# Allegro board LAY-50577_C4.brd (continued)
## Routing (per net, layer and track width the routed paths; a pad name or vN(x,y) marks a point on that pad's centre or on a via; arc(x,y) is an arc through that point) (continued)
N103962432: length 19.6
  TOP w0.119: J53.2 5.12,115.79 5.32,115.59 6.6,115.59 6.71,115.7 7.51,115.7 7.94,115.27 9.05,115.27 U51.3 9.66,115.21 v1(9.99,115.54)
  BOTTOM w0.119: v1(9.99,115.54) 10.01,115.52 10.27,115.52 11.54,116.79 12.36,116.79 12.48,116.91 12.48,117.14 12.59,117.26 12.83,117.26 12.95,117.14 12.95,116.91 13.07,116.79 21.83,116.79 R812.1
N103962456: length 19.4
  TOP w0.119: J53.3 5.14,115.14 5.34,115.34 6.7,115.34 6.84,115.21 U51.2 7.66,115.21 7.84,115.02 8.4,115.02 8.71,114.72 9.59,114.72 9.95,115.08 10.32,115.08 v1(10.42,114.98)
  BOTTOM w0.119: R813.1 21.7,116.55 11.64,116.55 10.43,115.34 10.43,115.31 10.42,115.3 v1(10.42,114.98)
N103962999: length 2.4
  TOP w0.127: R815.1 12.2,99.12 U52.A3
N103963079: length 4
  TOP w0.127: U52.A1 12.7,99.92 13.32,100.54 R817.1 ; R816.2 R817.1 ; R817.1 R818.2
N104012170: length 2.4
  TOP w0.127: R821.1 JP7.2
N104016532: length 1.7
  TOP w0.127: R831.1 44.18,108.15 U58.7
N104016534: length 1.8
  TOP w0.127: R832.1 43.8,107.65 U58.6
N104016623: length 2.7
  TOP w0.127: R902.2 R835.1 33.89,101.04 33.75,100.9 U57.4
N104016749: length 2.3
  TOP w0.127: R833.1 29.58,105.76 R903.2 30.21,105.74 30.32,105.63 U59.4
N104016751: length 2.5
  TOP w0.127: U56.4 34.52,97.35 R901.2 R834.1
N104017363: length 5.8
  TOP w0.203: U60.2 42.73,97.67 42.81,97.59 v1(42.81,97.49)
  BOTTOM w0.381: R842.1 41.56,98.26 ; R842.1 41.13,97.85 ; R842.1 40.7,98.26 ; JP5.2 42.07,93.04 ; JP5.2 40.19,93.04 ; JP5.2 41.13,93.98 ; JP5.2 41.13,92.1
N104034773: length 2.2
  TOP w0.127: R846.1 38.09,113.88 U61.14
N104034775: length 1.9
  TOP w0.127: R847.1 37.7,114.12 37.96,114.38 U61.13
N104034777: length 2.2
  TOP w0.127: R848.2 42.65,113.88 U61.3
N104034811: length 4
  TOP w0.127: U61.9 40.12,117.43 R849.2 39.09,117.43 38.58,117.95 Q15.3
N104034835: length 2
  TOP w0.127: R1078.2 43.03,115.78 42.64,115.38 U61.6
N104105294: length 1.2
  TOP w0.127: R854.2 34.89,107.64 D30.A
N104105296: length 1.2
  TOP w0.127: D29.A 32.35,107.64 R853.2
N104315925: length 3.8
  TOP w0.381: U42.3 68.86,106.2 C277.1 C276.1 R653.2
N104599012: length 1.9
  TOP w0.127: v1(113.14,124.28) 113.25,124.17 D31.C
  BOTTOM w0.127: v1(113.14,124.28) 112.81,123.95 Q19.3
N104599036: length 3.2
  BOTTOM w0.127: R875.1 116.31,125.68 R876.1 114.91,125.15 114.99,125.07 Q19.1
N104599080: length 2
  TOP w0.127: D32.C 113.25,120.49 v1(113.01,120.73)
  BOTTOM w0.127: Q20.3 112.81,120.53 v1(113.01,120.73)
N104599094: length 2.7
  BOTTOM w0.127: Q20.1 116.43,120.86 R879.1 117.7,120.85 R878.1
N104600982: length 2
  TOP w0.127: D33.C 113.25,116.93 v1(113.01,117.17)
  BOTTOM w0.127: v1(113.01,117.17) 112.81,116.97 Q21.3
N104600995: length 2.7
  BOTTOM w0.127: R885.1 117.7,117.29 R886.1 115.04,117.29 Q21.1
N104601399: length 1.9
  TOP w0.127: D35.C 113.25,113.25 113.01,113.49 v1(113.01,113.53)
  BOTTOM w0.127: v1(113.01,113.53) 112.81,113.32 Q23.3
N104601413: length 2.7
  BOTTOM w0.127: R891.1 117.7,113.74 R892.1 115.06,113.74 Q23.1
N104649727: length 1.7
  TOP w0.127: U48.7 160.69,27.19 R804.2
N104649749: length 2.9
  TOP w0.127: R800.2 R803.1 160,18.87 160.04,18.92 U48.1
N104653681: length 1.9
  TOP w0.381: 55.23,134.06 54.75,134.54 J60.1
N104654018: length 21.2
  TOP w0.381: 49.27,137.42 J60.7 48.47,138.55 ; C528.1 49.82,133.3 ; C528.1 49.38,133.7 ; C528.1 R1327.1 ; 56.38,135.42 J60.9 55.67,134.61 ; 58.42,138.55 J60.8 57.62,137.42 ; R1327.1 48.24,133.7 ; R1327.1 47.81,133.3 ; 51.22,134.61 J60.6 50.51,135.42
  L3_INT_1 w0.381: J60.6 51.22,136.24 ; J60.6 51.22,134.61 ; J60.6 51.93,135.42 ; J60.6 50.51,135.42 ; 55.67,134.61 J60.9 ; J60.9 55.67,136.24 ; J60.9 56.38,135.42 ; J60.9 54.96,135.42 ; J60.7 50.06,138.55 ; J60.7 49.27,137.42 ; J60.7 48.49,138.55 ; 56.84,138.55 J60.8 ; J60.8 57.62,137.42 ; J60.8 58.41,138.55
N104654056: length 2.4
  TOP w0.127: U74.3 53.02,133.98 52.8,134.21 J60.4
N105054073: length 10.8
  TOP w0.127: J67.9 188.7,26.24 187.68,27.26 R1021.1
  BOTTOM w0.127: J67.9 J67.7 J67.5 J67.3
N105054132: length 15.2
  TOP w0.127: R1022.2 188.06,24.97 192.89,24.97 193.78,25.86 193.78,32.46 192.39,33.85 J67.4
N105054134: length 5.7
  TOP w0.127: R1023.2 188.82,32.46 191.24,32.46 J67.6
N105054136: length 5.2
  TOP w0.127: J67.8 191.24,29.92 R1024.2
N105054138: length 5.8
  TOP w0.127: R1025.2 189.2,27.38 191.24,27.38 J67.10
N105070687: length 3.7
  TOP w0.127: U115.5 62.25,93.46 62.46,93.68 62.46,94.56 R1028.2
N105070691: length 2.2
  TOP w0.127: R1033.2 57.87,93.06 U115.7
N105070693: length 2.2
  TOP w0.127: R1034.1 57.87,92.26 U115.9
N105070700: length 3.2
  TOP w0.127: R1036.2 R1035.1 62.72,92.03 62.48,92.26 U115.2
N105070744: length 2
  TOP w0.127: U115.8 R1029.1
N105070750: length 2.4
  TOP w0.127: U115.6 58.36,93.46 R1030.1
N105070826: length 3.3
  TOP w0.127: U115.3 62.59,92.66 62.85,92.92 R1031.1 R1038.2
N105070844: length 3.2
  TOP w0.127: R1032.1 62.85,94.05 62.85,93.55 62.36,93.06 U115.4
N105164696: length 3.4
  TOP w0.127: R1043.1 R1044.1 187.46,87.67 v1(188.58,87.67)
  BOTTOM w0.127: U117.2 v1(188.58,87.67)
N105165362: length 3.1
  BOTTOM w0.127: U118.2 116.59,87.67 R1045.2 R1046.2
N105165453: length 2.5
  BOTTOM w0.127: R1047.1 R1048.1 153.39,123.77 153.57,123.95 U119.2
N105216901: length 111.3
  TOP w0.127: R1067.2 v1(148.82,84.79)
  L3_INT_1 w0.127: v1(145.4,38.05) 145.46,38.11 145.46,46.1 143.68,47.88 143.68,67.47 149.28,73.07 149.28,74.68 149.08,74.88 149.08,78.95 152.63,82.5 152.63,83.26 151.62,84.28 149.33,84.28 v1(148.82,84.79)
  BOTTOM w0.127: v1(145.4,38.05) 145.9,38.56 158.1,38.56 167.24,29.42 168.15,29.42 169.3,28.27 171.38,28.27 173.21,26.44 173.21,19 173.59,18.62 173.59,15.45 J69.3
N105216903: length 114.1
  TOP w0.127: R1064.2 v1(143.74,84.79)
  L3_INT_1 w0.127: v1(143.74,84.79) 144.63,83.9 151.36,83.9 152.13,83.14 152.13,82.5 148.57,78.95 148.57,74.75 148.88,74.45 148.88,73.99 148.37,73.48 147.94,73.48 147.3,72.85 147.3,71.78 143.3,67.78 143.3,47.72 145.07,45.94 145.07,38.75 v1(144.38,38.05)
  BOTTOM w0.127: J69.5 179.69,7.91 172.83,14.77 172.83,18.37 172.45,18.75 172.45,23.32 168.64,27.13 168.64,27.94 167.93,28.65 166.99,28.65 158.1,37.54 144.89,37.54 v1(144.38,38.05)
N105216905: length 101
  TOP w0.127: R1069.2 v1(140.95,65.99)
  BOTTOM w0.127: J69.7 177.15,8.71 172.07,13.79 172.07,18.11 170.92,19.26 170.92,23.73 158.83,35.82 148.62,35.82 147.68,34.88 143.24,34.88 141.9,36.22 134.66,36.22 130.23,40.65 130.23,44.73 130.66,45.16 132.57,45.16 137.78,50.37 138.66,50.37 140,51.7 140,54.83 141.97,56.8 141.97,63.76 140.95,64.77 v1(140.95,65.99)
N105216907: length 94.9
  TOP w0.127: v1(141.33,62.06) R1066.2
  BOTTOM w0.127: v1(141.33,62.06) 141.33,56.97 138.79,54.43 138.79,51.64 138.54,51.39 137.71,51.39 132.25,45.93 130.35,45.93 129.62,45.2 129.62,40.24 134.25,35.61 141.11,35.61 142.47,34.24 159.46,34.24 170.16,23.54 170.16,11.25 J69.9
N105216909: length 83
  TOP w0.127: R1068.2 v1(138.32,51.9)
  BOTTOM w0.127: v1(138.32,51.9) 137.78,51.9 132.19,46.31 130.19,46.31 129.31,45.43 129.31,40.04 134.05,35.3 140.78,35.3 142.14,33.94 159.32,33.94 168.38,24.88 168.38,12.27 172.07,8.59 J69.11
N105216911: length 87.9
  TOP w0.127: R1065.2 v1(139.05,56.47)
  BOTTOM w0.127: v1(139.05,56.47) 138.66,56.47 137.81,55.62 137.81,53.13 131.75,47.07 129.87,47.07 128.63,45.83 128.63,40.85 127.87,40.08 127.87,39.58 128.12,39.32 128.94,39.32 133.57,34.69 140.37,34.69 141.74,33.33 158.63,33.33 166.1,25.86 166.1,11.51 169.53,8.08 J69.13
N105216913: length 91.8
  TOP w0.127: R1073.2 138.02,60.28 v1(137.65,60.28)
  BOTTOM w0.127: J69.15 166.99,8.46 165.46,9.98 165.46,25.48 158.22,32.72 141.2,32.72 139.84,34.08 133.11,34.08 128.63,38.56 127.49,38.56 126.4,39.65 126.4,40.39 127.89,41.88 127.89,46.16 129.56,47.83 131.38,47.83 137.01,53.47 137.01,56.26 137.98,57.23 137.98,59.95 v1(137.65,60.28)
N105216915: length 105.9
  TOP w0.127: R1071.2 126.01,67.08 127.13,67.08 127.4,66.82 129.46,66.82 129.86,66.41 134.15,66.41 v1(134.85,65.71)
  BOTTOM w0.127: J69.17 163.43,7.83 163.43,25.48 156.8,32.11 151.9,32.11 151.11,31.32 141.46,31.32 140.06,32.72 132.44,32.72 131.93,33.23 131.93,34.11 128.25,37.8 127.23,37.8 125.71,39.32 125.71,40.97 126.98,42.24 126.98,46.33 129.24,48.59 130.92,48.59 136.23,53.9 136.23,60.78 134.85,62.16 v1(134.85,65.71)
N105216917: length 93.9
  TOP w0.127: R1072.2 132.7,62.69 v1(132.57,62.82)
  BOTTOM w0.127: v1(132.57,62.82) 135.36,60.02 135.36,58.5 134.73,57.86 134.73,53.29 130.79,49.35 128.93,49.35 125.96,46.39 125.96,43.39 124.95,42.37 124.95,39.07 126.98,37.04 127.74,37.04 131.04,33.73 131.04,32.97 131.96,32.06 139.58,32.06 141.08,30.56 153.02,30.56 153.27,30.81 157.21,30.81 162.67,25.35 162.67,7.57 J69.19
N105217449: length 111.1
  TOP w0.127: R1056.1 v1(152.63,84.79)
  L3_INT_1 w0.127: v1(146.41,38.05) 147.61,39.25 147.61,44.67 144,48.28 144,67.36 149.61,72.97 149.61,74.73 150.27,75.39 150.27,79.63 153.78,83.14 153.78,83.64 v1(152.63,84.79)
  BOTTOM w0.127: J69.4 180.83,5.67 180.83,7.49 173.21,15.11 173.21,18.49 172.83,18.88 172.83,26.29 171.22,27.89 169.17,27.89 168.01,29.05 167.1,29.05 158.1,38.05 v1(146.41,38.05)
N105217451: length 111.3
  TOP w0.127: R1054.1 v1(157.97,84.79)
  L3_INT_1 w0.127: v1(146.41,37.04) 147.96,38.59 147.96,44.88 145.01,47.83 145.01,54.94 145.4,55.32 145.4,62.09 144.76,62.72 144.76,67.26 150.41,72.91 150.41,73.7 151.11,74.4 151.11,79.07 154.16,82.12 156.06,82.12 157.97,84.03 v1(157.97,84.79)
  BOTTOM w0.127: v1(146.41,37.04) 146.54,37.16 157.97,37.16 166.9,28.23 167.84,28.23 168.26,27.82 168.26,27 172.07,23.19 172.07,18.62 172.45,18.24 172.45,14.43 178.54,8.34 178.54,5.41 J69.6
N105217453: length 97.3
  TOP w0.127: v1(139.43,54.24) 134.97,54.24 133.58,55.63 R1059.1
  BOTTOM w0.127: J69.8 176,5.41 176,8.84 170.54,14.3 170.54,23.6 158.63,35.51 148.95,35.51 147.99,34.55 142.93,34.55 141.57,35.91 134.46,35.91 129.92,40.44 129.92,44.96 130.51,45.54 132.41,45.54 137.74,50.88 138.54,50.88 139.43,51.77 v1(139.43,54.24)
N105217455: length 91
  TOP w0.127: v1(147.3,47.2) 147.36,47.25 R1057.1
  BOTTOM w0.127: J69.10 175.88,3 185.27,3 187.05,4.78 187.05,36.02 174.73,48.34 163.43,48.34 162.54,47.45 147.55,47.45 v1(147.3,47.2)
N105217467: length 89.7
  TOP w0.127: v1(138.66,55.7) 138.41,55.96 R1058.1
  BOTTOM w0.127: J69.12 170.8,5.54 170.8,8.71 168,11.51 168,24.64 159.01,33.63 141.94,33.63 140.58,35 133.85,35 129.01,39.84 129.01,45.7 130.02,46.71 132.06,46.71 138.28,52.94 138.28,55.32 v1(138.66,55.7)
N105217469: length 78.8
  TOP w0.127: v1(190.99,49.74) 190.48,50.24 180.71,50.24 R1055.1
  BOTTOM w0.127: v1(190.99,49.74) 187.43,46.18 187.43,4.62 185.43,2.62 171.18,2.62 J69.14
N105217471: length 100.9
  TOP w0.127: R1063.1 v1(135.87,64.47)
  BOTTOM w0.127: v1(135.87,64.47) 137.27,64.47 138.54,63.2 138.54,62.44 138.28,62.18 138.28,56.87 137.43,56.02 137.43,53.33 131.55,47.45 129.72,47.45 128.25,45.98 128.25,40.97 127.49,40.21 127.49,39.45 128,38.94 128.76,38.94 133.31,34.39 140.04,34.39 141.41,33.02 158.49,33.02 165.77,25.74 165.77,10.7 168.32,8.14 168.32,5.6 J69.16
N105217473: length 96.4
  TOP w0.127: v1(137.27,62.82) R1061.1
  BOTTOM w0.127: J69.18 165.72,5.54 165.72,8.33 163.81,10.24 163.81,26.62 158.02,32.41 141,32.41 139.64,33.78 132.78,33.78 128.38,38.18 127.36,38.18 126.07,39.47 126.07,40.69 127.49,42.12 127.49,46.3 129.4,48.21 131.17,48.21 136.61,53.65 136.61,60.12 137.27,60.78 v1(137.27,62.82)
N105217475: length 100
  TOP w0.127: R1062.1 131.3,64.83 v1(131.44,64.97)
  BOTTOM w0.127: J69.20 163.18,5.54 163.18,7.44 163.05,7.57 163.05,25.41 156.66,31.8 152.1,31.8 151.24,30.94 141.33,30.94 139.91,32.36 132.16,32.36 131.55,32.97 131.55,33.86 128,37.42 127.11,37.42 125.33,39.19 125.33,41.23 126.47,42.37 126.47,46.36 129.08,48.97 130.84,48.97 135.24,53.37 135.24,56.47 135.79,57.03 135.79,60.23 131.44,64.58 v1(131.44,64.97)
N105256205: length 1.9
  TOP w0.127: U61.12 37.44,114.88 R1074.1
N105256208: length 2.1
  TOP w0.127: U61.11 37.83,115.38 R1075.1
N105257045: length 2
  TOP w0.127: U61.4 42.65,114.38 43.03,114 R1076.2
N105257114: length 1.8
  TOP w0.127: R1077.2 43.42,114.88 U61.5
N105291076: length 7.3
  TOP w0.127: v1(26.07,112.16) 25.54,112.68 U55.L13
  BOTTOM w0.127: v1(26.07,112.16) 26.07,111.89 26.9,111.05 26.9,109.83 25.74,108.66 JP7.1
N105373803: length 1.3
  TOP w0.127: D39.A R1088.2
N105401122: length 4.6
  TOP w0.127: J71.1 173.86,94.96 R1093.2 173.09,94.94 172.82,95.21 R1094.2
N105406651: length 3.8
  TOP w0.508: J1.3 35.79,19.38 35.29,18.87 D41.C
N105406660: length 3.5
  TOP w0.508: J1.5 D42.C
N105406670: length 3.6
  TOP w0.508: D43.C 41.26,18.87 40.87,19.26 J1.7
N105488843: length 1.2
  TOP w0.127: R686.1 171.56,120.59 Y3.1
N105541476: length 1.9
  TOP w0.127: U121.2 56.26,28.11 v1(55.81,27.66)
  BOTTOM w0.127: v1(55.81,27.66) 55.81,27.82 C479.1
N105544244: length 2.7
  TOP w0.127: U121.1 55.76,28.43 R1097.2
N105551352: length 4.1
  TOP w0.127: C480.1 53.07,28.65 53.7,29.29 53.7,30.46 54.06,30.82 U121.29
N105554209: length 7.7
  TOP w0.127: C170.1 50.27,19.64 50.27,15.83 52.3,13.8 J28.4
N105554214: length 3.7
  TOP w0.127: J28.3 51.54,19.9 C180.1
N105554264: length 7.2
  TOP w0.508: J28.9 60.56,17.73 TP1068.1
N105572670: length 17.7
  BOTTOM w0.127: R1191.2 67.29,19.38 67.29,7.02 J32.11
N105572737: length 8.7
  TOP w0.127: C507.1 73.13,17.23 73.13,15.83 75.16,13.8 J32.4
N105572739: length 4.9
  TOP w0.127: J32.3 74.4,16.98 C508.1
N105593482: length 28.1
  BOTTOM w0.127: R1190.1 68.31,18.62 67.67,17.99 67.67,7.28 70.3,4.65 80.38,4.65 J32.13
N105605244: length 1.6
  TOP w0.254: U123.2 88.01,27.66 v1(87.99,27.64)
  BOTTOM w0.381: C518.1 v1(87.99,27.64)
N105605262: length 5.8
  TOP w0.127: U123.29 85.81,30.82 85.49,30.5 85.49,30.11 85.63,29.97 85.63,29.03 84.59,27.99 83.88,27.99 83.55,28.32 C510.1
N105605885: length 2.7
  TOP w0.127: U123.1 87.51,28.43 R1286.2
N105847330: length 2.4
  TOP w0.127: R448.2 R446.2 115.68,103.5 116.02,103.84 U125.8
N105847333: length 2.7
  TOP w0.127: v1(116.19,107.65) 116.02,107.82 U125.1
  BOTTOM w0.127: R450.2 v1(116.19,107.65) R453.2
N105847380: length 1.4
  TOP w0.127: R1319.2 114.66,103.46 114.72,103.51 U125.6
N105851215: length 2.6
  TOP w0.127: R1324.2 R1321.2 62.59,108.03 62.89,107.73 U126.8
N105851217: length 2.6
  TOP w0.127: R1323.2 R1322.2 62.89,101.12 U126.1
N105851251: length 1.7
  TOP w0.127: R1320.2 64.19,108.11 U126.6
N105870078: length 1.7
  TOP w0.127: R1316.2 SW5.5
N105870081: length 1.7
  TOP w0.127: R1315.2 SW5.6
N105870084: length 1.7
  TOP w0.127: SW5.7 R1314.2
N106014504: length 1.1
  TOP w0.254: U312.2 119.18,61.5 C530.1
N106191377: length 6.7
  BOTTOM w0.127: J102.1 59.42,98.88 59.42,102.31 58.72,103.01 U362.4
N106191386: length 8.8
  BOTTOM w0.127: U366.4 50.29,98.77 J104.1
N106191553: length 5.1
  BOTTOM w0.127: J103.1 54.97,101.3 54.08,102.19 54.08,103 U365.4
N106192914: length 4.9
  TOP w0.127: R1900.1 101.19,38.19 101.54,37.84 U356.3 C578.1 R2113.2
N106192924: length 7.3
  TOP w0.127: J92.1 101.45,41.61 101.39,41.55 U356.2 100.69,40.04 100.56,40.17 100.56,40.72 100.44,40.85 R2090.2 99.8,40.22 99.93,40.08 C577.1 R1900.2
N106193141: length 10.9
  TOP w0.127: U361.2 34.02,41.77 34.27,42.02 34.27,43.26 33.13,44.4 28.3,44.4 J90.1
N106193157: length 17.9
  TOP w0.127: J91.1 30.59,49.86 35.16,45.29 35.16,39.96 34.37,39.16 U361.6
N106193171: length 6.2
  TOP w0.127: U361.10 37.3,39.81 36.3,38.81 J93.1
N106193408: length 8.7
  TOP w0.127: U361.12 37.46,41.12 33,36.65 J94.1
N106193418: length 13.6
  TOP w0.127: J88.1 31.86,46.43 34.78,43.51 34.78,40.85 34.4,40.46 U361.4
N106193455: length 4.8
  TOP w0.127: U361.8 37.91,38.51 37.69,38.3 37.69,37.8 J89.1
N106204967: length 7.3
  TOP w0.081: U369.C4 88.51,118.45 87.39,118.45 87.13,118.19 86.7,118.19 86.58,118.07
  TOP w0.127: TP1024.1 83.29,116.92 85.71,116.92 86.09,117.3 86.09,117.58 86.58,118.07
N106204969: length 5.1
  TOP w0.081: U369.D4 89.51,118.95 89.51,120.75
  TOP w0.127: 89.51,120.75 90.62,121.86 90.62,122.55 C593.1
N106205008: length 7.7
  TOP w0.081: 88.51,121.1 88.51,119.59 88.65,119.45 89.01,119.45 U369.D5
  TOP w0.127: 88.51,121.1 88.16,121.45 88.16,123.05 89.39,124.28 TP1025.1
N106205010: length 8.5
  TOP w0.081: 91.17,120.6 90.79,120.6 90.51,120.33 90.51,120.1 90.37,119.95 90.16,119.95 90.01,119.8 90.01,119.45 U369.E5
  TOP w0.127: 91.17,120.6 92.18,121.62 92.18,122.76 93.07,123.65 93.07,124.92 TP1026.1
N106205029: length 17.9
  TOP w0.254: R2136.2 v1(83.67,117.55) ; C592.1 v1(94.3,120.86) 94.72,120.86 95.1,121.24 P2.1
  BOTTOM w0.254: v1(94.3,120.86) 91.29,120.86 88.88,118.44 86.47,118.44 85.58,117.55 v1(83.67,117.55)
N106205042: length 6.1
  TOP w0.081: U369.F5 90.51,119.45 91.28,119.45 91.8,119.97 92.31,119.97 92.69,119.59
  TOP w0.127: TP1027.1 93.2,119.59 92.69,119.59
N106205065: length 7.1
  TOP w0.081: U369.E6 89.76,119.83 90.01,120.08 90.01,120.51 90.61,121.11 90.79,121.11
  TOP w0.127: 90.79,121.11 91.42,121.74 91.42,123.01 91.55,123.14 91.55,124.92 TP1028.1
N106205067: length 5.1
  TOP w0.254: R2137.1 94.73,123.14 P2.2
N106205081: length 4.7
  TOP w0.081: 89.76,120.57 U369.E7
  TOP w0.127: 89.76,120.57 91.12,121.92 91.12,123.57 90.79,123.9 TP1029.1
N106205130: length 7.8
  TOP w0.081: U369.E1 89.76,117 90.91,115.85 90.91,115.32
  TOP w0.127: R2138.1 92.06,112.72 J98.2 90.91,113.87 90.91,115.32
N106205151: length 13.4
  TOP w0.081: 90.53,115.32 90.53,115.85 89.51,116.87 89.51,117.95 U369.D3
  TOP w0.127: 90.53,115.32 90.53,109.93 J97.2 92.06,108.4 R2139.1
N106205159: length 9.7
  TOP w0.081: 90.15,115.32 90.15,115.85 89.26,116.74 U369.D1
  TOP w0.127: J100.2 90.15,109.81 90.15,115.32
N106205163: length 5.8
  TOP w0.081: 89.77,115.32 89.77,115.85 89.01,116.61 89.01,117.45 U369.D2
  TOP w0.127: J99.2 89.77,113.74 89.77,115.32
N106205177: length 2.8
  TOP w0.081: R2140.2 92.7,121.75 91.14,120.2 U369.G7
N106205193: length 5
  TOP w0.081: 91.04,120.86 90.66,120.86 90.26,120.46 U369.F7
  TOP w0.127: 91.04,120.86 91.75,121.57 91.75,122.84 92.31,123.4 TP1030.1
N106205804: length 4.3
  TOP w0.254: R2141.2 85.32,106.5 C596.1 C594.2 83.41,107.27 83.29,107.39 J95.1
N106205806: length 4.3
  TOP w0.254: R2142.2 85.32,112.72 C597.1 C595.2 83.54,113.5 83.42,113.62 J96.1
N106205931: length 4.3
  TOP w0.254: J95.2 83.42,104.85 83.54,104.97 C598.1 C596.2 85.32,105.75 R2143.2
N106205933: length 4.3
  TOP w0.254: J96.2 83.29,111.08 83.41,111.2 C599.1 C597.2 85.32,111.97 R2144.2
N106205994: length 7.4
  TOP w0.081: U369.E4 90.01,118.95 91.54,118.95 91.8,119.2 92.56,119.2
  TOP w0.127: TP1022.1 95.1,116.66 94.34,117.43 94.34,117.93 93.71,118.57 93.2,118.57 92.56,119.2
N106206003: length 3.7
  TOP w0.081: TP1023.1 92.81,118.45 90.51,118.45 U369.F4
N106206005: length 2.2
  TOP w0.127: R2146.1 92.15,116.28 91.23,117.2 U369.G1
N106206024: length 4.6
  TOP w0.081: U369.E3 90.01,117.95 90.01,117.59 90.16,117.45 90.39,117.45 90.51,117.32 90.51,117.09 90.81,116.8 91.29,116.8
  TOP w0.127: 91.29,116.8 92.06,116.03 92.06,115.91 R2145.1
N106206063: length 8.4
  TOP w0.081: U369.G6 91.25,119.7 91.78,120.22 92.56,120.22
  TOP w0.127: TP1031.1 96.63,117.17 93.58,120.22 92.56,120.22
N106206071: length 5.6
  TOP w0.081: U369.C5 88.62,119.2 88.37,119.45 88.16,119.45 88.01,119.6 88.01,119.8 87.86,119.95 87.61,119.95
  TOP w0.127: C588.1 84.82,122.74 87.61,119.95
N106207432: length 3.6
  TOP w0.254: J101.4 103.01,132 102.98,132.03 L37.2
N106207455: length 9.3
  TOP w0.254: L38.2 109.54,127.71 J101.1
N106207457: length 25.6
  TOP w0.081: U369.B4 88.01,118.95 87.1,118.95 86.95,118.8 86.14,118.8 v1(86.09,118.85)
  TOP w0.254: R2147.1 v1(100.18,129.87)
  BOTTOM w0.254: v1(100.18,129.87) 97.52,127.21 88.16,127.21 86.52,125.56 86.52,119.84 86.09,119.41 v1(86.09,118.85)
N106348035: length 13.9
  TOP w0.127: v1(105.89,74.04) U6.E15
  BOTTOM w0.127: R2157.1 116.17,78.92 114,78.92 108.95,73.87 106.06,73.87 v1(105.89,74.04)
N106559790: length 29
  BOTTOM w0.127: 45.57,19.64 43.8,17.86 43.8,8.59 47.35,5.03 57.14,5.03 J28.13
N106561451: length 21.3
  BOTTOM w0.127: 44.3,19.64 43.16,18.49 43.16,8.29 46.8,4.65 49.34,4.65 J28.12
N106615195: length 1.4
  TOP w0.127: U15.A4 v1(85.92,81.51)
  BOTTOM w0.127: v1(85.92,81.51) 86.08,81.35 R335.2
N106641917: length 4.2
  TOP w0.127: J105.1 157.19,94.84 U44.21
N107062928: length 2.6
  TOP w0.127: R464.2 R465.2 129.65,104.35 v1(129.77,104.22)
  BOTTOM w0.127: U416.2 129.27,104.73 v1(129.77,104.22)
N107431729: length 6.2
  TOP w0.508: TP1069.1 62.46,15.83 J28.10
N107431851: length 6.7
  TOP w0.508: TP1071.1 88.25,15.45 84.94,15.45 J32.10
N107431853: length 7
  TOP w0.508: 82.02,16.34 88.88,16.34 TP1070.1
N107755006: length 3.7
  TOP w0.127: TP1056.1 118.11,2.89 J134.19
N107755030: length 4
  TOP w0.127: TP1057.1 120.11,3.62 J134.27
N107755069: length 5.9
  TOP w0.127: TP1058.1 121.39,3.63 123.04,3.63 123.61,4.2 J134.41
N107755071: length 4.4
  TOP w0.127: R283.1 124.44,1.48 122.79,1.48 R280.1 TP1059.1
N107755107: length 5.1
  TOP w0.127: J134.56 127.11,12.53 127.87,13.29 128.89,13.29 129.65,14.05 R2586.1
N107755114: length 7.4
  TOP w0.127: J134.58 127.61,12.52 128,12.91 129.14,12.91 130.28,14.05 TP1064.1
N107755120:
  vias: v1(129.9,4.52) v1(129.9,3.63)
N107755122: length 5.4
  TOP w0.127: R2587.1 130.92,13.92 129.52,12.52 128.25,12.52 128.11,12.39 J134.60
N999437150: length 1.4
  TOP w0.127: R32.2 124.69,35.12 D6.A
N1021983941: length 1.5
  TOP w0.127: R33.2 124.69,38.8 D7.A
N1038045711: length 3.8
  BOTTOM w0.381: 149.95,21.67 C169.1 ; C169.1 150.36,21.24 ; C169.1 150.36,22.1 ; R379.2 150.3,20.96 ; R379.2 150.92,20.02 ; R379.2 150.3,19.08
N1045989930: length 1.5
  TOP w0.127: R877.2 114.8,121.88 D31.A
N1045991261: length 1.5
  TOP w0.127: R880.2 114.8,118.33 D32.A
N1046010301: length 1.5
  TOP w0.127: D33.A 114.8,114.77 R887.2
N1046013920: length 1.5
  TOP w0.127: R893.2 114.8,111.22 D35.A

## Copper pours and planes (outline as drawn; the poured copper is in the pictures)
5V_SDA_PSW on TOP: 10.65,100.03 10.65,99.39 9.89,98.63 9.12,98.63 8.87,98.88 8.87,100.54 9,100.66 10.01,100.66
5V_SYS on TOP: 106.15,39.07 107.8,39.07 107.8,35.38 107.93,35.26 108.57,35.26 108.95,34.88 108.95,34.11 108.69,33.86 106.41,33.86 105.77,34.5 105.77,38.69
5V_SYS on TOP: 171.05,28.4 173.08,28.4 173.21,28.27 173.21,27.89 173.08,27.76 171.05,27.76
5V_SYS on TOP: 145.52,95.07 152.13,95.07 152.25,94.95 152.25,90.63 150.86,89.23 148.06,89.23 147.94,89.36 147.94,91.26 147.43,91.77 138.92,91.77 138.79,91.9 138.79,93.42 138.92,93.55 140.95,93.55 141.08,93.68 144.76,93.68 145.27,94.19 145.27,94.82
5V_SYS on TOP: 85.83,135.59 88.25,135.59 88.75,135.08 88.75,131.52 88.12,130.89 85.83,130.89 85.07,131.65 85.07,134.83
5V_SYS on TOP: 42.14,22.68 41.76,22.3 34.65,22.3 34.4,22.56 32.24,22.56 31.86,22.94 31.86,29.8 32.37,30.3 40.24,30.3 42.14,28.4
5V_SYS on BOTTOM: 132.57,4.78 134.35,4.78 134.47,4.65 134.47,2.49 134.35,2.36 132.57,2.36 132.44,2.49 132.44,4.65
5V_SYS on BOTTOM: 147.43,92.15 174.1,92.15 175.24,93.3 192.51,93.3 192.64,93.42 192.64,95.71 192.51,95.84 166.1,95.84 165.21,94.95 147.43,94.95 147.17,94.69 147.17,92.41 ; 1 cut-out
5V_SYS on L3_INT_1: 154.92,57.1 157.97,57.1 162.16,52.91 162.16,35.26 169.02,28.4 177.27,28.4 178.8,29.92 178.8,62.56 186.92,70.69 189.85,70.69 190.48,70.06 190.48,68.02 186.8,64.34 186.8,54.82 187.43,54.18 187.43,53.04 184.26,49.86 184.26,29.42 179.43,24.59 162.29,24.59 153.78,33.1 153.78,55.96
5V_SYS on L4_PWR_1: 9,138.38 93.45,138.38 93.83,138 93.83,121.36 93.58,121.11 64.62,121.11 61.7,124.03 53.7,124.03 48.37,129.36 16.49,129.36 16.49,109.55 13.19,106.25 13.19,101.93 18.65,96.47 20.17,96.47 20.17,34.37 22.18,32.36 43.39,32.36 44.94,30.81 44.94,23.7 46.34,22.3 98.41,22.3 103.36,17.35 109.84,17.35 112.25,19.76 112.25,25.35 107.17,30.43 107.17,34.62 107.42,34.88 110.85,34.88 123.04,22.68 141.59,22.68 150.48,13.79 173.21,13.79 174.73,15.32 174.73,23.57 174.1,24.21 174.1,25.73 171.18,28.65 162.29,28.65 156.44,34.5 156.44,42.37 159.11,45.04 175.49,45.04 181.84,51.39 181.84,65.36 184.89,68.4 184.89,83.64 186.92,85.68 190.23,85.68 191.62,87.07 191.62,95.71 191.75,95.84 193.27,95.84 193.4,95.71 193.4,86.82 189.34,82.76 189.34,73.74 193.53,69.55 193.53,15.06 180.19,1.73 133.33,1.73 132.44,2.62 132.44,12.27 130.28,14.43 116.95,14.43 113.26,10.75 101.33,10.75 94.47,17.6 15.35,17.6 11.16,21.8 11.16,91.01 8.68,93.49 3.09,93.49 1.5,95.07 1.5,108.54 2.77,109.81 5.06,109.81 6.08,110.82 6.08,135.46
5V_USB_OTG1 on TOP: 185.78,57.36 187.81,57.36 188.07,57.61 188.07,58.63 188.19,58.75 189.21,58.75 189.59,58.37 189.59,56.34 189.46,56.21 188.19,56.21 187.94,55.96 187.94,55.45 187.81,55.32 187.31,55.32 186.92,55.7 185.78,55.7 185.65,55.83 185.65,57.23
5V_USB_OTG2 on TOP: 190.35,72.21 190.23,72.09 188.7,72.09 188.58,72.21 188.58,73.61 188.83,73.87 190.23,73.87 190.35,73.74
GND on TOP: 90.53,47.32 90.4,47.45 90.4,51.64 90.53,51.77 94.06,51.77 94.47,51.36 94.47,47.68 94.11,47.32
GND on TOP: 30.84,27.76 30.84,24.46 29.19,22.81 25.51,22.81 24.62,21.92 24.62,17.48 24.24,17.1 23.98,17.1 23.6,17.48 23.6,17.86 22.71,18.75 21.7,18.75 20.94,17.99 20.05,17.99 19.67,18.37 19.67,22.81 19.54,22.94 17.76,22.94 17.38,22.56 14.59,22.56 14.33,22.81 14.33,26.24 15.22,27.13 19.03,27.13 19.48,27.57 19.54,27.51 19.54,29.03 19.79,29.29 20.81,29.29 21.06,29.03 21.06,27.38 21.44,27 24.87,27 25.76,27.89 30.71,27.89
GND on TOP: 121.9,48.34 122.15,48.59 123.81,48.59 124.06,48.34 124.06,45.42 124.19,45.42 124.57,45.04 124.57,44.27 124.82,44.02 125.96,44.02 126.47,43.51 126.47,41.23 126.35,41.1 122.15,41.1 121.9,41.35
GND on TOP: 140.44,22.81 142.22,22.81 142.86,22.18 142.86,19.38 142.35,18.87 140.32,18.87 139.93,19.26 139.93,22.3
GND on TOP: 16.49,35.77 18.27,35.77 18.4,35.64 18.4,33.1 18.27,32.97 16.62,32.97 16.36,33.23 16.36,35.64
GND on TOP: 51.87,87.94 51.87,90.33 52.05,90.5 55.61,90.5 55.94,90.17 55.94,88.8 55.61,88.47 53.45,88.47 52.81,87.84 51.97,87.84
GND on TOP: 186.04,57.61 185.91,57.74 184.26,57.74 184,57.99 184,58.75 184.26,59.01 187.81,59.01 187.94,58.88 187.94,57.74 187.81,57.61
GND on TOP: 187.18,74.12 186.92,74.37 186.92,76.15 187.18,76.41 189.72,76.41 189.85,76.28 189.85,74.25 189.72,74.12
GND on BOTTOM: 133.08,6.94 134.6,6.94 134.73,6.81 134.73,5.29 134.6,5.16 133.08,5.16 132.95,5.29 132.95,6.81
GND on BOTTOM: 106.91,6.68 108.44,6.68 108.57,6.56 108.57,4.52 108.44,4.4 106.91,4.4 106.79,4.52 106.79,6.56
GND on BOTTOM: 140.44,23.32 142.09,23.32 142.6,22.81 142.6,21.29 142.09,20.78 140.19,20.78 139.93,21.03 139.93,22.81
GND on L2_GND_1, L5_GND_2: 112,139.36 194.36,139.36 194.36,0.64 0.64,0.64 0.64,139.36 106.25,139.36 106.25,138.07 112,138.07
GND_RJ45_SHELL0 on TOP: 65.26,8.84 43.92,8.84 43.8,8.97 43.8,13.03 43.92,13.16 48.62,13.16 49.13,12.65 61.07,12.65 61.7,13.29 65.39,13.29 65.51,13.16 65.51,9.1
GND_RJ45_SHELL1 on TOP: 119.61,131.9 120.76,130.76 133.2,130.76 134.35,131.9 137.52,131.9 137.65,131.78 137.65,127.33 137.39,127.08 115.93,127.08 115.8,127.21 115.8,131.78 115.93,131.9
GND_RJ45_SHELL2 on TOP: 7.85,52.15 9,53.29 9,65.74 7.85,66.88 7.85,69.93 7.98,70.06 12.43,70.06 12.68,69.8 12.68,48.47 12.55,48.34 7.98,48.34 7.85,48.47
GND_RJ45_SHELL3 on TOP: 7.85,77.55 9,78.69 9,91.14 7.85,92.28 7.85,95.2 7.98,95.33 12.55,95.33 12.68,95.2 12.68,73.87 12.55,73.74 7.98,73.74 7.85,73.87
GND_RJ45_SHELL4 on TOP: 88.12,8.84 66.78,8.84 66.66,8.97 66.66,13.03 66.78,13.16 71.48,13.16 71.99,12.65 83.93,12.65 84.56,13.29 88.12,13.29 88.25,13.16 88.25,8.97
P3V3_SDA on TOP: 14.2,108.41 15.98,108.41 16.11,108.28 16.11,105.23 15.86,104.98 13.57,104.98 13.44,105.11 13.44,107.65
P3V3_SDA on L4_PWR_1: 18.01,122.76 35.41,122.76 39.48,118.7 39.48,117.68 38.08,116.28 38.08,112.6 41,109.68 41,107.52 36.81,103.33 33.89,103.33 31.98,101.42 31.98,98.63 31.73,98.38 29.83,98.38 29.7,98.5 29.7,102.69 30.59,103.58 30.59,105.36 29.44,106.5 26.52,106.5 25.38,105.36 25.38,97.61 24.75,96.98 18.78,96.98 13.7,102.06 13.7,106.12 17.13,109.55 17.13,121.87
P5V_SDA on TOP: 11.03,113.24 13.82,113.24 14.2,112.85 14.2,108.66 13.7,108.16 11.16,108.16 10.65,108.66 10.65,112.85
P5V_SDA on TOP: 11.03,103.33 12.17,103.33 12.43,103.08 12.43,101.04 11.66,100.28 11.16,100.28 10.78,100.66 10.78,103.08
P5V_SDA on TOP: 9.51,122.76 10.9,122.76 11.28,122.38 11.28,118.19 11.03,117.93 9.63,117.93 9,118.57 9,122.25
P5V_SDA on L3_INT_1: 7.35,122.76 12.17,122.76 12.81,122.13 12.81,119.2 15.09,116.92 20.81,116.92 21.19,116.54 21.19,114.25 20.24,113.3 16.81,113.3 16.11,112.6 16.11,102.82 15.35,102.06 8.24,102.06 6.33,103.96 6.33,121.74
VCC_I3C on TOP: 166.86,24.21 167.62,23.45 167.62,22.81 167.11,22.3 165.72,22.3 165.72,25.61 165.84,25.73 166.6,25.73 166.86,25.48
VCC_I3C on L4_PWR_1: 173.72,25.48 173.72,24.08 174.35,23.45 174.35,19.64 174.1,19.38 168.64,19.38 166.35,21.67 166.35,27.89 166.73,28.27 170.92,28.27
VDD_1V8 on TOP: 89.52,135.46 90.79,135.46 91.29,134.95 91.29,133.43 91.67,133.05 92.44,133.05 92.69,132.79 92.69,131.27 92.44,131.02 89.64,131.02 89.01,131.65 89.01,134.95
VDD_1V8 on TOP: 124.69,59.39 124.82,59.26 124.82,58.63 125.58,57.86 125.58,55.83 125.33,55.58 122.79,55.58 122.15,54.94 118.47,54.94 118.22,55.2 118.22,58.88 118.73,59.39
VDD_1V8 on BOTTOM: 90.91,132.79 97.14,132.79 99.55,135.21 102.34,135.21 102.47,135.08 102.47,133.43 102.34,133.3 100.44,133.3 98.15,131.02 90.66,131.02 90.53,131.14 90.53,132.41
VDD_1V8 on L3_INT_1: 118.98,56.21 119.87,56.21 120.12,56.47 120.12,59.01 119.23,59.9 118.6,59.9 117.2,61.29 117.2,66.5 122.92,72.21 122.92,76.53 120.25,79.2 120.25,82.88 118.73,84.41 112.25,84.41 112.12,84.28 112.12,83.14 112.25,83.01 117.33,83.01 118.34,81.99 118.34,73.87 115.55,71.07 115.55,68.53 114.15,67.13 114.15,59.9 115.93,58.12 117.07,58.12
VDD_1V8 on L4_PWR_1: 102.6,73.74 103.99,73.74 104.63,74.37 104.63,76.15 110.72,82.25 113.14,82.25 113.39,82.5 113.39,83.64 113.14,83.9 108.82,83.9 102.34,77.42 102.34,73.99
VDD_1V8 on L4_PWR_1: 112,139.02 160.51,139.02 165.08,134.44 165.08,130.38 167.37,128.09 167.37,126.06 164.83,123.52 164.83,107.77 156.19,99.14 133.33,99.14 129.27,95.07 125.96,95.07 124.95,96.09 124.95,97.87 130.92,103.84 132.31,103.84 134.47,106 151.11,106 159.24,114.12 159.24,129.75 156.57,132.41 138.92,132.41 138.41,131.9 138.41,125.94 136.63,124.16 117.07,124.16 113.65,127.59 100.69,127.59 100.31,127.97 100.31,138.64 100.69,139.02 106.25,139.02 106.25,138.07 112,138.07
VDD_AON_3V3 on TOP: 119.87,50.5 120.25,50.88 121.9,50.88 122.03,50.75 122.03,47.7 121.65,47.32 117.46,47.32 117.33,47.45 117.33,50.37 117.46,50.5
VDD_AON_IN on TOP: 119.87,51.77 117.33,51.77 117.2,51.89 117.2,54.05 117.33,54.18 121.77,54.18 122.03,53.93 122.03,51.51 121.9,51.39 120.25,51.39
VDD_BBSM_3V3 on TOP: 113.9,46.94 114.03,46.81 114.03,45.42 113.65,45.04 110.72,45.04 110.6,45.16 110.6,46.69 110.85,46.94
VDD_SOC_IN on TOP: 85.58,47.45 87.36,47.45 87.74,47.07 92.69,47.07 92.82,46.94 92.82,44.43 92.54,44.15 85.73,44.15 85.45,44.43 85.45,47.32
VDD_SOC_IN on L4_PWR_1: 85.88,46 87.36,44.53 93.02,44.53 99.87,51.37 99.87,56.28 105.14,61.55 105.14,69.5 104.22,70.41 103.71,70.41 102.98,71.15 102.98,71.71 102.72,71.96 99.17,71.96 98.41,71.2 98.41,69.17 99.04,68.53 99.04,67.13 97.14,65.23 97.14,61.29 85.88,50.04
VDDA_ADC_3P3 on TOP: 117.55,61.04 119.74,61.04 119.74,60.78 119.36,60.4 117.55,60.4
ADC_1V8_IN on TOP: 113.77,59.01 113.77,60.15 113.14,60.78 113.14,62.56 113.52,62.94 117.84,62.94 117.96,62.82 117.96,62.56 117.26,61.86 117.26,61.42 116.44,61.42 115.93,60.91 115.93,58.75 115.8,58.63 114.15,58.63
ADC_1V8_IN on BOTTOM: 112.38,63.07 114.15,63.07 114.53,62.69 114.53,61.93 114.03,61.42 111.99,61.42 109.96,63.45 108.69,63.45 108.31,63.83 108.31,64.21 108.82,64.72 110.72,64.72
ADC_1V8_IN on L3_INT_1: 103.26,70.44 107.88,70.44 110.22,68.1 110.22,63.81 110.12,63.71 108.57,63.71 108.31,63.96 108.31,66.37 107.42,67.26 103.31,67.26 103.13,67.44 103.13,70.31
DBUG_5V on TOP: 56.37,132.67 56.37,130.51 56.5,130.38 58.02,130.38 58.15,130.51 58.15,132.67 57.89,132.92 56.62,132.92
DBUG_5V on L3_INT_1: 47.61,131.14 58.02,131.14 58.15,131.02 58.15,125.55 57.51,124.92 49.76,124.92 49.51,125.17 49.51,126.7 49,127.21 47.73,127.21 46.84,128.09 46.84,130.38
DC_5V_IN on TOP: 15.35,14.94 17.33,12.96 19.18,12.96 19.67,12.47 19.67,9.73 19.28,9.35 12.93,9.35 11.03,11.25 11.03,19.51 11.41,19.89 14.71,19.89 15.35,19.26
DCDC_3V3 on TOP: 29.7,37.16 29.83,37.04 29.83,35.38 29.32,34.88 25.76,34.88 23.73,32.84 23.09,32.84 22.59,32.34 22.59,31.57 21.32,31.57 21.32,32.21 21.19,32.34 19.28,32.34 18.9,32.72 18.9,36.91 19.16,37.16
DCDC_3V3_PG on TOP: 21.57,27.26 24.36,27.26 25.13,28.02 25.13,30.05 23.98,30.05 23.98,29.29 23.09,28.4 21.95,28.4 21.57,28.02
FLASH_VCC on TOP: 123.55,61.17 123.81,61.42 126.22,61.42 126.35,61.29 126.35,59.77 126.22,59.64 123.68,59.64 123.55,59.77
FLASH_VCC on BOTTOM: 152.51,64.21 153.9,64.21 154.16,64.47 155.56,64.47 155.81,64.21 155.81,62.82 155.56,62.56 154.54,62.56 154.29,62.82 154.29,63.32 153.9,63.71 152.51,63.71
FLASH_VCC on L3_INT_1: 105.14,124.16 115.55,124.16 121.14,118.57 130.28,118.57 134.85,114 134.85,111.01 135.62,110.25 135.62,104.73 136,104.35 140.7,104.35 143.49,107.14 175.62,107.14 176.38,106.38 189.34,106.38 190.73,104.98 190.73,86.69 186.92,82.88 186.92,77.29 170.41,60.78 156.06,60.78 154.41,62.44 154.41,64.09 156.19,65.86 166.1,65.86 177.27,77.04 177.27,90.88 173.72,94.44 173.72,102.06 172.45,103.33 159.11,103.33 158.35,104.09 143.36,104.09 141.71,102.44 134.73,102.44 133.2,103.96 133.2,109.81 131.04,111.97 131.04,114.12 128.63,116.54 120,116.54 113.26,123.27 107.17,123.27 106.79,122.89 105.14,122.89 105.01,123.01 105.01,124.03
FLASH_VCC on L3_INT_1: 100.95,73.74 104.25,73.74 105.01,72.98 105.01,71.96 104.37,71.33 102.47,71.33 100.69,73.1 100.69,73.48
FLASH_VCC on L4_PWR_1: 100.95,124.16 108.31,124.16 108.69,123.78 108.69,110.95 106.03,108.28 104.63,108.28 100.31,112.6 100.31,123.52
FLASH_VCC on L4_PWR_1: 103.61,70.56 103.23,70.94 103.23,71.96 103.49,72.21 118.73,72.21 125.58,65.36 146.79,65.36 150.35,68.91 153.27,68.91 155.3,66.88 155.3,62.94 154.79,62.44 128.89,62.44 126.22,59.77 124.57,59.77 124.19,60.15 124.19,60.78 116.95,68.02 116.95,70.18 116.57,70.56
MCU_DCDC_IN on TOP: 78.21,48.08 78.09,48.21 78.09,49.35 80.37,51.64 84.94,51.64 85.2,51.39 85.2,48.08 85.07,47.96 83.04,47.96 82.91,48.08
MCU_DCDC_IN on L4_PWR_1: 98.41,69.04 98.91,68.53 98.91,67.39 96.75,65.23 96.75,61.55 83.29,48.08 78.97,48.08 77.96,49.1 77.96,56.34 90.66,69.04
NVCC_BBSM on L4_PWR_1: 102.72,58.75 103.23,58.75 103.61,58.37 103.61,49.48 101.58,47.45 99.42,47.45 98.91,47.96 98.91,49.81 100.31,51.21 100.31,56.34
NVCC_SD on TOP: 135.87,97.87 136,97.74 136,94.31 136.38,93.93 138.16,93.93 138.28,93.8 138.28,91.9 138.16,91.77 134.6,91.77 134.47,91.9 134.47,97.74 134.6,97.87
PHY0_AVDD33 on BOTTOM: 53.73,31.04 54.95,31.04 55.1,30.89 55.1,27.74 55.53,27.31 56.98,27.31 57.59,27.92 57.59,28.35 57.87,28.63 60,28.63 60.13,28.5 60.13,27.74 60.05,27.66 59.37,27.66 59.19,27.49 59.19,27.23 58.73,26.77 54.84,26.77 53.63,27.99 53.63,30.94
PHY0_VDD33 on L4_PWR_1: 51.34,38.33 57.64,38.33 62.19,33.78 64.67,33.78 65.92,32.54 65.92,30.05 64.85,28.98 60.28,28.98 59.9,28.6 59.9,27.26 60.43,26.72 62.29,26.72 62.52,26.49 62.52,22.86 62.21,22.56 46.84,22.56 45.45,23.95 45.45,32.44
PHY1_DVDD33 on TOP: 128.5,107.9 129.9,107.9 130.03,108.03 130.03,109.04 129.77,109.3 128.5,109.3 128.25,109.04 128.25,108.16
PHY1_DVDD33 on BOTTOM: 128.5,109.43 130.54,109.43 130.66,109.3 130.66,108.79 130.54,108.66 128.5,108.66 128.38,108.79 128.38,109.3
PHY1_DVDD33 on L3_INT_1: 116.31,110.57 120.12,110.57 122.28,108.41 127.62,108.41 129.01,109.81 132.57,109.81 132.95,109.43 132.95,105.23 131.93,104.22 131.04,104.22 128,101.17 115.55,101.17 115.3,101.42 115.3,109.55
PHY1_DVDDRG on L3_INT_1: 117.2,115.01 122.41,115.01 128,109.43 128,109.17 127.62,108.79 122.54,108.79 120.5,110.82 116.19,110.82 114.92,109.55 114.92,102.57 114.28,101.93 113.65,101.93 113.14,102.44 113.14,110.95
PHY4_AVDD33 on BOTTOM: 85.76,30.81 86.72,30.81 86.82,30.71 86.82,28.1 87.61,27.31 88.5,27.31 89.69,28.5 91.78,28.5 91.8,28.48 91.8,27.99 91.6,27.79 91.14,27.79 90.79,27.43 90.79,27.23 90.4,26.85 87.43,26.85 85.6,28.68 85.6,30.66
PHY4_VDD33 on L4_PWR_1: 83.09,38.33 89.39,38.33 93.94,33.78 96.42,33.78 96.68,33.53 96.68,29.06 96.6,28.98 93.81,28.98 93.38,28.55 93.38,27.38 94.27,26.49 94.27,23.37 93.83,22.94 79.23,22.94 78.97,23.19 78.97,34.22
SDRAM_3V3 on TOP: 54.59,87.71 54.97,87.33 54.97,85.93 54.72,85.68 50.4,85.68 50.15,85.93 50.15,87.45 50.4,87.71
SDRAM_3V3 on L4_PWR_1: 90.25,69.27 66.78,45.8 59.29,45.8 49.13,55.96 49.13,85.17 49.51,85.55 52.56,85.55 57.21,90.2 87.92,90.2 90.25,87.86
SENSOR_3V3 on TOP: 117.84,47.07 119.61,47.07 119.74,46.94 119.74,46.05 119.36,45.67 117.96,45.67 117.71,45.93 117.71,46.94
SENSOR_3V3 on TOP: 93.71,135.59 94.47,135.59 95.23,134.83 95.23,133.56 96.5,132.29 96.5,131.14 96.37,131.02 93.33,131.02 93.07,131.27 93.07,134.95
SENSOR_3V3 on TOP: 111.74,6.68 114.15,6.68 114.28,6.56 114.28,2.62 114.15,2.49 111.74,2.49 111.61,2.62 111.61,6.56
SENSOR_3V3 on TOP: 169.78,49.61 188.07,49.61 193.66,44.02 193.66,35.26 193.15,34.75 186.29,34.75 183.24,37.8 169.91,37.8 169.4,38.31 169.4,49.23
SENSOR_3V3 on TOP: 110.22,48.59 111.61,48.59 111.74,48.47 111.74,47.2 111.49,46.94 110.34,46.94 110.09,47.2 110.09,48.47
SENSOR_3V3 on TOP: 77.58,44.91 77.58,47.58 77.7,47.7 82.78,47.7 83.17,47.32 83.17,44.91 83.04,44.78 77.7,44.78
SENSOR_3V3 on TOP: 127.49,58.63 126.47,58.63 126.22,58.37 125.46,58.37 125.08,58.75 125.08,59.26 125.2,59.39 126.35,59.39 126.73,59.77 127.62,59.77 127.74,59.64 127.74,58.88
SENSOR_3V3 on TOP: 121.82,61.14 122.33,61.14 122.74,60.73 123.22,60.73 123.3,60.66 123.3,59.64 123.17,59.51 122.23,59.51 121.82,59.92
SENSOR_3V3 on TOP: 164.19,26.11 165.33,26.11 165.46,25.99 165.46,25.1 165.33,24.97 164.19,24.97 164.06,25.1 164.06,25.99
SENSOR_3V3 on TOP: 49,89.99 51.42,89.99 51.67,89.74 51.67,87.96 51.54,87.84 49.26,87.84 48.75,88.34 48.75,89.74
SENSOR_3V3 on TOP: 172.95,123.9 174.48,123.9 174.61,123.78 174.61,122.25 174.35,122 173.08,122 172.83,122.25 172.83,123.78
SENSOR_3V3 on BOTTOM: 112.5,6.56 112.5,4.27 112.38,4.14 110.72,4.14 110.6,4.27 110.6,6.56 110.72,6.68 112.38,6.68
SENSOR_3V3 on BOTTOM: 138.41,134.44 139.43,134.44 139.68,134.19 140.82,134.19 141.08,133.94 141.08,132.29 140.19,131.4 138.92,131.4 138.66,131.65 138.66,133.05 138.28,133.43 138.28,134.32
SENSOR_3V3 on L3_INT_1: 82.4,84.79 84.31,84.79 86.59,82.5 96.75,82.5 100.44,78.82 100.44,72.85 102.22,71.07 102.72,71.07 103.05,70.74 103.05,67.49 102.85,67.29 102.37,67.29 102.09,67.57 102.09,68.4 100.95,69.55 97.9,69.55 97.64,69.8 97.64,70.18 97.9,70.44 98.28,70.44 98.28,71.71 98.02,71.96 97.26,71.96 97.26,75.52 92.94,79.83 82.4,79.83 80.24,81.99 80.24,82.63
SENSOR_3V3 on L3_INT_1: 112.38,4.14 106.41,4.14 106.15,4.4 106.15,16.21 111.99,22.05 125.84,22.05 132.19,15.7 132.19,13.67 131.81,13.29 116.44,13.29 112.5,9.35 112.5,4.27
SENSOR_3V3 on L3_INT_1: 188.58,37.8 193.27,37.8 193.78,37.29 193.78,12.78 186.29,5.29 184.26,5.29 183.11,6.43 183.11,10.37 188.07,15.32 188.07,37.29
SENSOR_3V3 on L4_PWR_1: outline of 116 points within 16.87,14.43 191.37,132.16 ; 2 cut-outs
SINC_AGND on L2_GND_1: 164.95,35.51 177.91,35.51 178.42,35 178.42,30.05 177.27,28.91 169.4,28.91 164.45,33.86 164.45,35
SINC_VDDA_5V on TOP: 170.8,30.69 170.8,27.89 170.67,27.76 169.27,27.76 169.14,27.89 169.14,29.92 168.76,30.3 168.13,30.3 168,30.43 168,31.45 169.78,31.45 169.78,30.94 169.91,30.81 170.67,30.81
SINC_VDDA_5V on L3_INT_1: 175.49,35.13 175.49,29.42 174.99,28.91 169.4,28.91 169.14,29.16 169.14,31.45 173.21,35.51 175.11,35.51
SPDIF_BUF on BOTTOM: 146.67,21.92 148.44,21.92 148.95,21.41 148.95,19.26 148.57,18.87 146.92,18.87 146.41,19.38 146.41,21.67
SPDIF_COAX_OUT on TOP: 148.7,15.57 151.36,15.57 151.62,15.32 151.62,13.67 152,13.29 153.14,13.29 153.78,12.65 153.78,9.73 152.38,8.33 149.84,8.33 148.44,9.73 148.44,15.32
SPDIF_GND_PRI on TOP: 154.79,22.68 156.44,22.68 156.83,22.3 156.83,19.26 156.44,18.87 154.79,18.87 154.29,19.38 154.29,22.18
SPDIF_GND_PRI on BOTTOM: 154.67,23.32 156.32,23.32 156.83,22.81 156.83,21.29 156.32,20.78 154.41,20.78 154.16,21.03 154.16,22.81
SPDIF_OUT_PRI on TOP: 149.21,22.68 151.87,22.68 152.13,22.43 152.13,19.51 151.36,18.75 149.21,18.75 148.82,19.13 148.82,22.3
SPDIF_OUT_PRI on BOTTOM: 151.11,22.68 153.27,22.68 153.52,22.43 153.52,21.16 153.14,20.78 151.24,20.78 150.86,21.16 150.86,22.43
V_TGTMCU on L4_PWR_1: 21.82,123.27 35.79,123.27 39.86,119.2 39.86,117.55 38.33,116.03 38.33,112.85 41.51,109.68 41.51,107.52 36.87,102.89 34.08,102.89 32.24,101.04 32.24,98.38 31.86,98 29.7,98 29.32,98.38 29.32,102.82 30.33,103.84 30.33,104.98 29.19,106.12 26.65,106.12 25.76,105.23 25.76,97.36 26.9,96.22 41.64,96.22 46.34,100.92 46.34,120.22 41.13,125.43 21.82,125.43 21.19,124.79 21.19,123.9
VLDO_3V3 on TOP: 106.41,44.02 107.3,44.02 107.55,43.77 107.55,41.61 107.93,41.23 107.93,39.96 107.8,39.83 106.03,39.83 105.77,40.08 105.77,43.39
VLDO_3V3 on TOP: 111.61,44.78 113.65,44.78 113.77,44.66 113.77,43.89 113.39,43.51 111.99,43.51 111.49,44.02 111.49,44.66
VLDO_3V3 on L3_INT_1: 106.15,43.64 110.98,43.64 112.12,44.78 113.52,44.78 113.77,44.53 113.77,43.13 112.63,41.99 105.64,41.99 105.52,42.12 105.52,43
VSD_3V3 on BOTTOM: 138.28,136.22 142.98,136.22 143.49,135.71 147.94,135.71 148.19,135.46 148.19,134.06 147.94,133.81 145.65,133.81 145.52,133.94 143.36,133.94 142.6,134.7 139.68,134.7 139.3,135.08 138.28,135.08 138.03,135.33 138.03,135.97
WL_3V3 on TOP: 172.95,124.16 174.35,124.16 174.61,124.41 174.61,126.32 174.48,126.44 172.95,126.44 172.83,126.32 172.83,124.28
WL_3V3 on L4_PWR_1: 174.73,125.3 174.22,124.79 172.95,124.79 170.67,122.51 170.67,97.36 166.86,93.55 158.48,93.55 157.21,94.82 157.21,99.27 165.33,107.39 165.33,123.14 167.87,125.68 167.87,128.22 165.84,130.25 165.84,131.27 166.54,131.97 170.48,131.97 174.73,127.71
N100054243 on TOP: 29.95,16.33 29.65,16.64 25.56,16.64 25,17.2 25,21.72 25.58,22.3 34.02,22.3 34.52,21.8 34.52,18.62 32.24,16.33
N100054263 on TOP: 21.44,12.4 26.93,12.4 26.93,9.1 20.94,9.1 20.55,9.48 20.55,11.51
N100054299 on TOP: 21.44,12.78 26.02,12.78 26.17,12.93 26.17,13.19 26.27,13.29 32.75,13.29 33.25,13.79 33.25,15.83 33,16.08 29.7,16.08 29.42,16.36 27.72,16.36 27.72,16 27.41,15.7 22.84,15.7 22.33,15.19 21.7,15.19 21.32,14.81 21.32,12.91
N100054552 on TOP: 11.54,22.43 13.95,22.43 14.2,22.18 14.2,20.4 13.95,20.14 11.66,20.14 11.41,20.4 11.41,22.3
N100068072 on TOP: 24.36,30.69 26.65,30.69 27.29,31.32 30.46,31.32 31.35,30.43 31.35,28.53 31.22,28.4 25.89,28.4 25.51,28.78 25.51,29.92 25.13,30.3 24.36,30.3
N100168474 on TOP: 183.88,56.21 184.89,56.21 185.65,55.45 186.8,55.45 187.05,55.2 187.05,53.93 186.92,53.8 184.77,53.8 184.64,53.93 183.24,53.93 183.11,54.05 183.11,55.45
N100171101 on TOP: 186.8,72.6 187.81,72.6 188.58,71.83 189.72,71.83 189.97,71.58 189.97,70.31 189.85,70.18 187.69,70.18 187.56,70.31 186.16,70.31 186.04,70.44 186.04,71.83
N100208849 on TOP: 126.85,45.29 126.98,45.42 126.98,48.34 127.23,48.59 129.27,48.59 129.39,48.47 129.39,45.93 128.89,45.42 128.89,40.59 128.76,40.46 126.98,40.46 126.85,40.59
N100211328 on TOP: 124.95,44.4 124.82,44.53 124.82,45.16 124.44,45.54 124.44,48.59 122.66,50.37 122.66,55.07 122.79,55.2 125.33,55.2 125.84,55.7 125.84,57.61 126.6,58.37 128.25,58.37 128.5,58.12 128.5,56.09 129.14,55.45 129.14,51.26 126.73,48.85 126.73,45.42 126.6,45.29 126.6,44.53 126.47,44.4
N100224476 on TOP: 24.36,31.32 25.25,31.32 25.51,31.57 25.51,33.61 26.14,34.24 29.44,34.24 29.83,33.86 29.83,32.08 29.44,31.7 27.29,31.7 26.52,30.94 24.36,30.94
N100310756 on TOP: 136.38,99.52 139.81,99.52 140.06,99.27 140.06,96.34 139.81,96.09 138.79,96.09 138.28,95.58 138.28,94.69 138.16,94.57 136.38,94.57 136.25,94.69 136.25,99.39
N100999218 on BOTTOM: 129.27,111.58 131.3,111.58 131.43,111.46 131.43,109.93 131.17,109.68 127.87,109.68 127.49,110.06 127.49,111.08 128.23,111.81 129.04,111.81
N101209778 on TOP: 117.07,50.24 117.07,47.45 116.95,47.32 115.55,47.32 115.17,47.7 112.5,47.7 112.38,47.83 112.38,50.24 112.5,50.37 116.95,50.37
N101210175 on L4_PWR_1: 105.77,69.04 104.88,69.93 104.88,70.18 105.01,70.31 116.31,70.31 116.69,69.93 116.69,69.17 116.57,69.04
N101211864 on TOP: 93.33,57.1 93.2,56.97 87.23,56.97 86.98,57.23 86.98,60.91 88.56,62.5 88.56,63.01 90.53,64.98 95.87,64.98 95.99,64.85 95.99,62.94 93.33,60.28 ; 1 cut-out
N101211874 on TOP: 94.1,56.4 94.21,56.29 94.21,52.5 94.11,52.4 90.02,52.4 90.02,48.47 89.9,48.34 87.74,48.34 87.36,47.96 85.58,47.96 85.45,48.08 85.45,52.53 85.96,53.04 86.47,53.04 86.72,53.29 86.72,56.21 86.91,56.4
N101250307 on TOP: 133.84,13.92 134.98,13.92 135.62,13.29 139.05,13.29 139.68,12.65 139.68,9.35 139.17,8.84 136.12,8.84 133.71,11.25 133.71,13.79
N101250309 on TOP: 140.57,15.7 142.09,15.7 142.35,15.45 142.35,6.94 139.93,4.52 136.76,4.52 136.25,5.03 136.25,7.83 136.51,8.08 139.17,8.08 140.19,9.1 140.19,15.32
N101250379 on BOTTOM: 132.44,21.54 134.09,21.54 134.73,20.91 134.73,19.51 134.47,19.26 132.31,19.26 132.06,19.51 132.06,21.16
N101250387 on TOP: 134.22,15.7 137.14,15.7 137.39,15.45 137.39,14.05 137.14,13.79 135.49,13.79 135.11,14.18 133.97,14.18 133.84,14.3 133.84,15.32
N101250389 on TOP: 135.62,22.94 137.52,22.94 137.9,22.56 137.9,19.76 136.89,18.75 135.24,18.75 134.85,19.13 134.85,22.18
N101250389 on BOTTOM: 137.14,22.94 139.05,22.94 139.3,22.68 139.3,21.16 138.92,20.78 137.01,20.78 136.63,21.16 136.63,22.43
N101250395 on BOTTOM: 135.24,22.43 136.12,22.43 136.38,22.18 136.38,21.03 136.89,20.53 136.89,19.38 136.25,18.75 135.24,18.75 134.98,19 134.98,22.18
N101250397 on BOTTOM: 130.16,22.68 132.31,22.68 132.44,22.56 132.44,21.92 131.81,21.29 131.81,20.02 131.43,19.64 130.16,19.64 129.77,20.02 129.77,22.3
N101250428 on BOTTOM: 146.03,21.41 146.03,19.26 146.92,18.37 146.92,16.33 146.79,16.21 144.25,16.21 144,16.46 144,21.41 144.13,21.54 145.9,21.54
N101250468 on TOP: 154.92,15.83 157.84,15.83 158.48,15.19 158.48,6.17 156.57,4.27 150.86,4.27 149.84,5.29 149.84,7.06 150.48,7.7 153.78,7.7 154.29,8.21 154.29,15.19
N102056178 on TOP: 153.27,94.31 155.05,94.31 158.35,91.01 158.35,88.22 158.22,88.09 155.3,88.09 155.17,88.22 155.17,89.87 153.14,91.9 153.14,94.19
N102544921 on TOP: 117.71,55.45 115.8,55.45 115.68,55.58 115.68,58.37 116.06,58.75 116.06,59.77 116.31,60.02 117.58,60.02 117.84,59.77 117.84,55.58
N103179532 on TOP: 189.72,68.79 194.29,68.79 194.36,68.71 194.36,65.86 191.5,65.86 191.37,65.74 191.37,63.96 191.12,63.71 189.72,63.71 189.46,63.96 189.46,68.53
N103179532 on TOP: 189.85,60.28 191.12,60.28 191.37,60.02 191.37,58.37 191.62,58.12 194.36,58.12 194.36,55.45 189.72,55.45 189.46,55.7 189.46,59.9
N103179532 on L3_INT_1: 191.75,67.13 194.16,67.13 194.36,66.93 194.36,56.54 193.91,56.09 190.86,56.09 189.85,57.1 189.85,65.23
N103179921 on TOP: 190.1,79.2 191.5,79.2 191.62,79.07 191.62,77.04 191.75,76.91 194.36,76.91 194.36,74.7 194.04,74.37 191.62,74.37 191.37,74.63 191.37,76.15 189.72,77.8 189.72,78.82
N103179921 on TOP: 191.24,86.82 194.36,86.82 194.36,83.39 193.02,83.39 192.77,83.64 192.77,84.79 192.64,84.91 191.75,84.91 191.5,84.66 191.5,82.76 191.37,82.63 189.59,82.63 188.96,83.26 188.96,85.55 189.72,86.31 190.73,86.31
N103179921 on L3_INT_1: 191.5,86.31 194.04,86.31 194.36,85.98 194.36,75.59 194.04,75.26 191.24,75.26 189.34,77.17 189.34,84.15
N103598440 on TOP: 107.11,50.69 109.77,50.69 109.84,50.62 109.84,46.81 108.06,46.81 107.93,46.69 107.04,46.69 106.91,46.81 106.91,48.15 106.95,48.18 106.95,50.53
N103598440 on L3_INT_1: 96.12,66.63 97.64,66.63 98.91,67.9 99.68,67.9 99.68,53.04 104.12,48.59 108.95,48.59 109.58,49.23 109.58,50.75 109.2,51.13 106.03,51.13 101.96,55.2 101.96,68.53 101.33,69.17 97.77,69.17 96.5,67.9 96.25,67.9 95.99,67.64 95.99,66.75
N103909102 on TOP: 165.72,22.05 166.73,22.05 167.87,20.91 167.87,20.65 166.86,19.64 165.72,19.64 165.59,19.76 165.59,21.92
N103961319 on TOP: 23.86,114.89 23.86,114.63 22.84,113.62 17.13,113.62 17,113.74 17,114.63 17.25,114.89
N103961455 on TOP: 21.06,112.98 22.59,112.98 23.48,113.87 23.6,113.87 23.73,113.74 23.73,113.62 23.35,113.24 23.35,112.35 22.71,111.71 21.06,111.71
N103962355 on TOP: 3.79,113.49 5.44,113.49 5.95,112.98 5.95,110.82 4.81,109.68 0.74,109.68 0.63,109.79 0.63,112.11 0.74,112.22 3.16,112.22 3.41,112.47 3.41,113.11
N103962355 on TOP: 1.76,122.63 4.93,122.63 5.44,122.13 5.44,117.05 5.19,116.79 3.92,116.79 2.65,118.06 0.87,118.06 0.63,118.3 0.63,121.51
N103962355 on L3_INT_1: 0.87,120.35 4.17,120.35 5.57,118.95 5.57,111.46 4.04,109.93 0.87,109.93 0.64,110.17 0.64,120.11
N103962365 on TOP: 6.33,120.6 8.24,120.6 8.62,120.22 8.62,118.57 9.89,117.3 9.89,116.92 9.12,116.16 8.49,116.16 7.85,116.79 7.85,117.81 7.47,118.19 6.84,118.19 6.58,117.93 6.58,117.3 6.33,117.05 5.82,117.05 5.82,120.09
N104017363 on BOTTOM: 40.24,98.5 42.65,98.5 43.29,97.87 43.29,94.57 42.53,93.8 42.53,92.28 42.02,91.77 40.62,91.77 39.99,92.41 39.99,93.8 40.87,94.69 40.87,96.85 40.11,97.61 40.11,98.38
N104653681 on TOP: 55.1,134.44 56.11,133.43 56.11,131.4 55.99,131.27 54.21,131.27 53.96,131.52 53.96,132.16 54.21,132.16 54.46,132.41 54.46,134.32 54.59,134.44
N104654018 on TOP: 47.44,139.36 50.4,139.36 50.4,137.62 51.67,136.35 51.67,134.19 50.65,133.17 47.61,133.17 47.35,133.43 47.35,139.27
N104654018 on TOP: 56.62,139.36 60.34,139.36 60.56,139.14 60.56,135.46 59.29,134.19 55.73,134.19 55.23,134.7 55.23,136.22 55.35,136.35 56.24,136.35 56.62,136.73
N104654018 on L3_INT_1: 48.46,139.36 58.56,139.36 59.04,138.89 59.04,136.1 57.13,134.19 49,134.19 48.11,135.08 48.11,139.02
N106014504 on TOP: 117.55,61.93 118.73,61.93 118.85,61.8 119.49,61.8 119.74,61.55 119.74,61.42 119.61,61.29 117.55,61.29
N106014760 on TOP: 121.77,62.13 122.71,62.13 123.17,61.67 123.17,61.29 122.99,61.12 122.74,61.12 122.49,61.37 121.77,61.37 121.77,61.62 122.43,61.62 122.43,61.88 121.77,61.88
N107755120 on TOP: 128,6.56 130.03,6.56 130.16,6.43 130.16,3.51 130.03,3.38 128.63,3.38 128,4.02
N107755120 on BOTTOM: 129.77,6.94 130.79,6.94 131.04,6.68 131.04,5.03 131.43,4.65 131.43,3.38 131.3,3.25 129.77,3.25 129.65,3.38 129.65,6.81
N1038045711 on BOTTOM: 149.46,22.43 150.35,22.43 150.6,22.18 150.6,21.03 151.11,20.53 151.11,19.38 150.48,18.75 149.46,18.75 149.21,19 149.21,22.18

Small or netless copper shapes (teardrops, artwork), in the pictures only: 1 on BOTTOM

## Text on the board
BOTTOM: 170-50577_REV C4 | 9 | L6_SS
Ref Des/Silkscreen Bottom: 11 | SECONDARY SILKSCREEN
